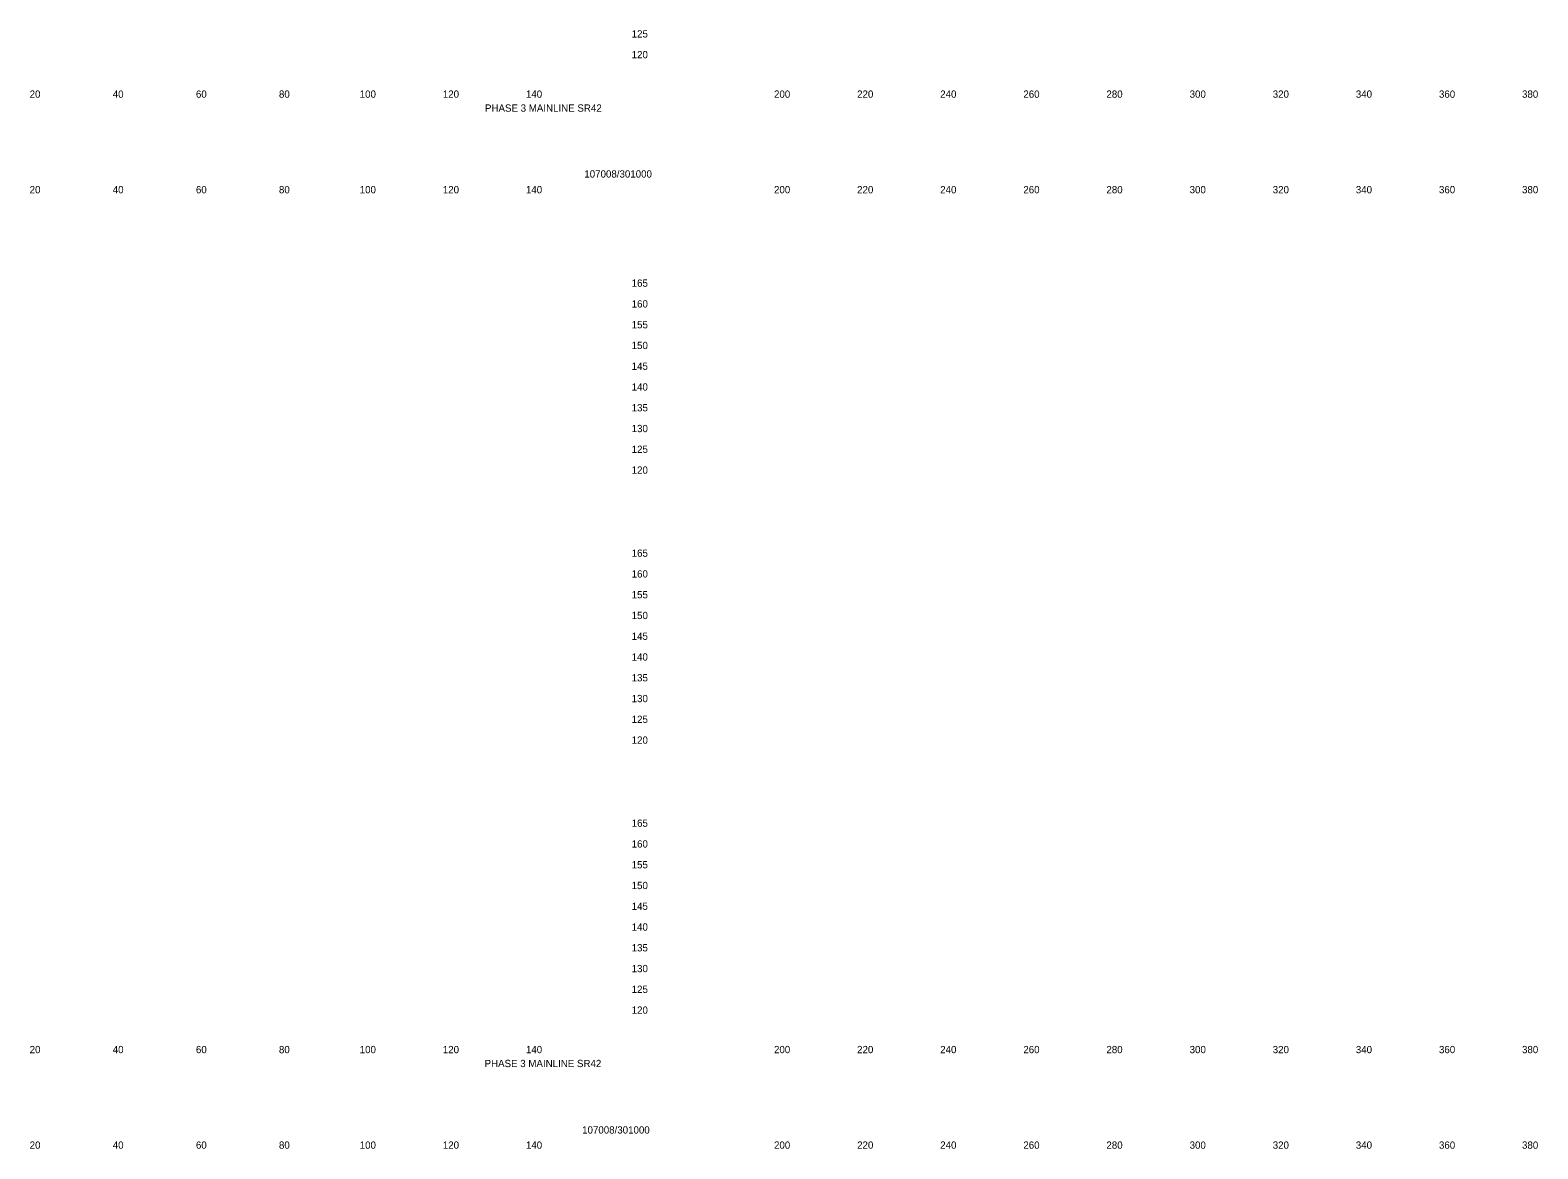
# Model space of a CAD drawing. Extents: x 21281 to 22024, y 6472 to 15198.
# Drawn here: x 21661.4 to 22024.2, y 7832.3 to 8101.6 of the extents above; entities that cross this region are included whole.
import ezdxf

# ---------------------------------------------------------------- set-up
doc = ezdxf.new("R2010")
doc.units = 0
doc.layers.add('Draft_XS_Grid', color=7, linetype='Continuous')
doc.layers.add('Draft_XS_Text', color=7, linetype='Continuous')

msp = doc.modelspace()

# ---------------------------------------------------------------- texts
at = {"layer": 'Draft_XS_Grid'}
for s, p in [('  125  ', (21804.84, 8099.84)), ('  120  ', (21804.84, 8094.84)), ('  165  ', (21804.84, 8039.84)), ('  160  ', (21804.84, 8034.84)), ('  155  ', (21804.84, 8029.84)), ('  150  ', (21804.84, 8024.84)), ('  145  ', (21804.84, 8019.84)), ('  140  ', (21804.84, 8014.84)), ('  135  ', (21804.84, 8009.84)), ('  130  ', (21804.84, 8004.84)), ('  125  ', (21804.84, 7999.84)), ('  120  ', (21804.84, 7994.84)), ('  165  ', (21804.84, 7974.84)), ('  160  ', (21804.84, 7969.84)), ('  155  ', (21804.84, 7964.84)), ('  150  ', (21804.84, 7959.84)), ('  145  ', (21804.84, 7954.84)), ('  140  ', (21804.84, 7949.84)), ('  135  ', (21804.84, 7944.84)), ('  130  ', (21804.84, 7939.84)), ('  125  ', (21804.84, 7934.84)), ('  120  ', (21804.84, 7929.84)), ('  165  ', (21804.84, 7909.84)), ('  160  ', (21804.84, 7904.84)), ('  155  ', (21804.84, 7899.84)), ('  150  ', (21804.84, 7894.84)), ('  145  ', (21804.84, 7889.84)), ('  140  ', (21804.84, 7884.84)), ('  135  ', (21804.84, 7879.84)), ('  130  ', (21804.84, 7874.84)), ('  125  ', (21804.84, 7869.84)), ('  120  ', (21804.84, 7864.84))]:
    msp.add_text(s, height=1.75, dxfattribs=at).set_placement(p)
at = {"layer": 'Draft_XS_Text'}
for s, p in [('  20  ', (21659.95, 8085.34)), ('  40  ', (21679.95, 8085.34)), ('  60  ', (21699.97, 8085.34)), ('  80  ', (21719.95, 8085.34)), ('  100  ', (21739.39, 8085.34)), ('  120  ', (21759.39, 8085.34)), ('  140  ', (21779.39, 8085.34)), ('  200  ', (21839.1, 8085.34)), ('  220  ', (21859.1, 8085.34)), ('  240  ', (21879.1, 8085.34)), ('  260  ', (21899.11, 8085.34)), ('  280  ', (21919.1, 8085.34)), ('  300  ', (21939.13, 8085.34)), ('  320  ', (21959.13, 8085.34)), ('  340  ', (21979.13, 8085.34)), ('  360  ', (21999.14, 8085.34)), ('  380  ', (22019.13, 8085.34)), ('PHASE 3 MAINLINE SR42', (21770.84, 8081.98)), ('107008/301000', (21794.75, 8066.12)), ('  20  ', (21659.95, 8062.34)), ('  40  ', (21679.95, 8062.34)), ('  60  ', (21699.97, 8062.34)), ('  80  ', (21719.95, 8062.34)), ('  100  ', (21739.39, 8062.34)), ('  120  ', (21759.39, 8062.34)), ('  140  ', (21779.39, 8062.34)), ('  200  ', (21839.1, 8062.34)), ('  220  ', (21859.1, 8062.34)), ('  240  ', (21879.1, 8062.34)), ('  260  ', (21899.11, 8062.34)), ('  280  ', (21919.1, 8062.34)), ('  300  ', (21939.13, 8062.34)), ('  320  ', (21959.13, 8062.34)), ('  340  ', (21979.13, 8062.34)), ('  360  ', (21999.14, 8062.34)), ('  380  ', (22019.13, 8062.34)), ('  20  ', (21659.95, 7855.34)), ('  40  ', (21679.95, 7855.34)), ('  60  ', (21699.97, 7855.34)), ('  80  ', (21719.95, 7855.34)), ('  100  ', (21739.39, 7855.34)), ('  120  ', (21759.39, 7855.34)), ('  140  ', (21779.39, 7855.34)), ('  200  ', (21839.1, 7855.34)), ('  220  ', (21859.1, 7855.34)), ('  240  ', (21879.1, 7855.34)), ('  260  ', (21899.11, 7855.34)), ('  280  ', (21919.1, 7855.34)), ('  300  ', (21939.13, 7855.34)), ('  320  ', (21959.13, 7855.34)), ('  340  ', (21979.13, 7855.34)), ('  360  ', (21999.14, 7855.34)), ('  380  ', (22019.13, 7855.34)), ('PHASE 3 MAINLINE SR42', (21770.74, 7851.99)), ('107008/301000', (21794.22, 7835.99)), ('  20  ', (21659.95, 7832.34)), ('  40  ', (21679.95, 7832.34)), ('  60  ', (21699.97, 7832.34)), ('  80  ', (21719.95, 7832.34)), ('  100  ', (21739.39, 7832.34)), ('  120  ', (21759.39, 7832.34)), ('  140  ', (21779.39, 7832.34)), ('  200  ', (21839.1, 7832.34)), ('  220  ', (21859.1, 7832.34)), ('  240  ', (21879.1, 7832.34)), ('  260  ', (21899.11, 7832.34)), ('  280  ', (21919.1, 7832.34)), ('  300  ', (21939.13, 7832.34)), ('  320  ', (21959.13, 7832.34)), ('  340  ', (21979.13, 7832.34)), ('  360  ', (21999.14, 7832.34)), ('  380  ', (22019.13, 7832.34))]:
    msp.add_text(s, height=1.75, dxfattribs=at).set_placement(p)

doc.saveas('drawing.dxf')
